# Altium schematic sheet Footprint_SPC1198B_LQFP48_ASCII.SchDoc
size A4; 项目编号: SPSZ2023-052501A; 项目名称: 三相PFC-2.2KW压机+700W风机
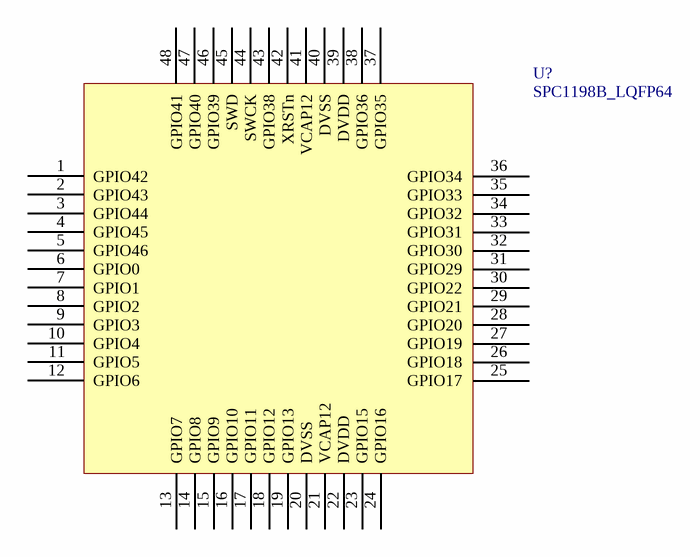
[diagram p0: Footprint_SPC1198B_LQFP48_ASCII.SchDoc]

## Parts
U?  SPC1198B_LQFP64  [LQFP-48-0.5]

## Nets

Not connected (* = marked no-connect by the designer): U? 1(GPIO42) 2(GPIO43) 3(GPIO44) 4(GPIO45) 5(GPIO46) 6(GPIO0) 7(GPIO1) 8(GPIO2) 9(GPIO3) 10(GPIO4) 11(GPIO5) 12(GPIO6) 13(GPIO7) 14(GPIO8) 15(GPIO9) 16(GPIO10) 17(GPIO11) 18(GPIO12) 19(GPIO13) 20(DVSS) 21(VCAP12) 22(DVDD) 23(GPIO15) 24(GPIO16) 25(GPIO17) 26(GPIO18) 27(GPIO19) 28(GPIO20) 29(GPIO21) 30(GPIO22) 31(GPIO29) 32(GPIO30) 33(GPIO31) 34(GPIO32) 35(GPIO33) 36(GPIO34) 37(GPIO35) 38(GPIO36) 39(DVDD) 40(DVSS) 41(VCAP12) 42(XRSTn) 43(GPIO38) 44(SWCK) 45(SWD) 46(GPIO39) 47(GPIO40) 48(GPIO41)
